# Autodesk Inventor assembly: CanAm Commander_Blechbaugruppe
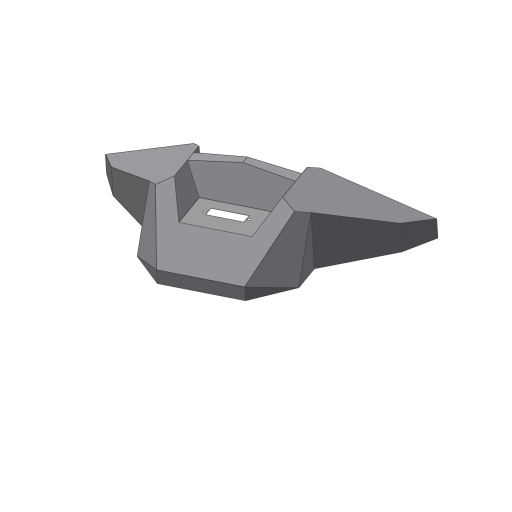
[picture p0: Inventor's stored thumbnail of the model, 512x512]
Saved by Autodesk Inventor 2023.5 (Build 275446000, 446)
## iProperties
Created: 2025-04
Part Number: CanAm Commander_Blechbaugruppe
Description: =<Beschreibung Zeile 1>
Document SubType Name: Assembly
Designer: wondraschek
Stock Number: =<L>x<B>x<D> oder <Size Designation> oder Ø<Size Designation> oder Ø<D>x<B>-<L> oder Ø<D>-<L>
Category: Prototypen
Company: KAME engineering
Title: Baugruppenvorlage
Subject: Prototypen
Author: wondraschek
Keywords: Baugruppen
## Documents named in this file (7)
- C:\Users\wondraschek.kame\OneDrive - KAME engineering\Privat\Projekte\CanAm Commander\CanAm Commander_Blechbaugruppe.iam
- C:\Users\wondraschek.kame\OneDrive - KAME engineering\Privat\Projekte\CanAm Commander\CanAm Commander_001_Blech.ipt
- C:\Users\wondraschek.kame\OneDrive - KAME engineering\Privat\Projekte\CanAm Commander\CanAm Commander_002_Blech.ipt
- C:\Users\wondraschek.kame\OneDrive - KAME engineering\Privat\Projekte\CanAm Commander\CanAm Commander_003_Blech.ipt
- C:\Users\wondraschek.kame\OneDrive - KAME engineering\Privat\Projekte\CanAm Commander\CanAm Commander_004_Blech.ipt
- C:\Users\wondraschek.kame\OneDrive - KAME engineering\Privat\Projekte\CanAm Commander\CanAm Commander_004_Blech_2.ipt
- D:\Inventor_Vorlagen_2023\Templates\Norm.iam
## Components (5 placed, 5 different names)
1. CanAm Commander_001_Blech:1
2. CanAm Commander_002_Blech:1
3. CanAm Commander_003_Blech:1
4. CanAm Commander_004_Blech:1
5. CanAm Commander_004_Blech_2:1
